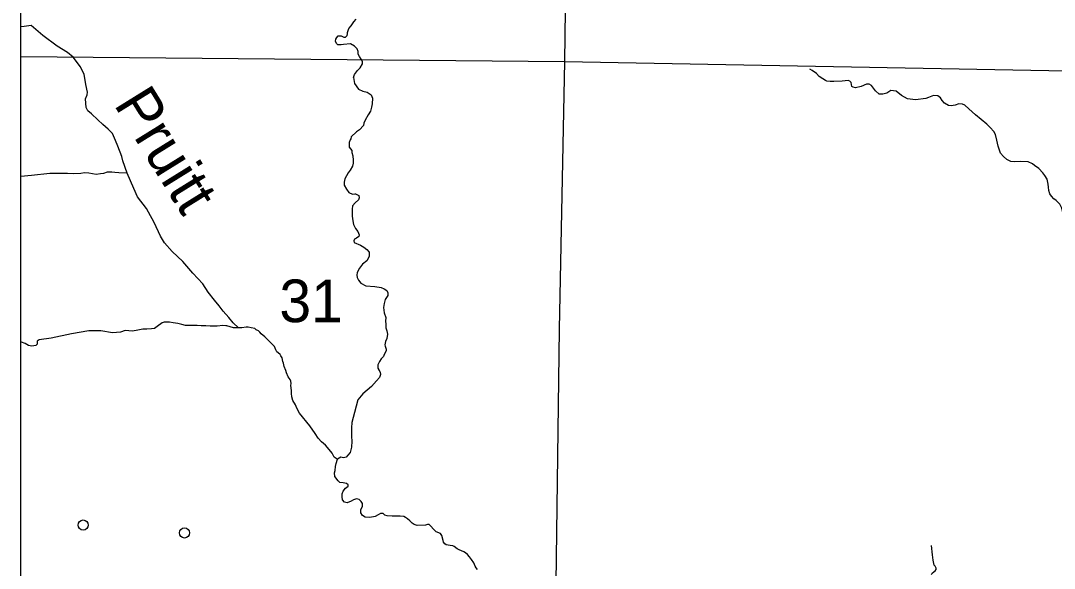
# Model space of a CAD drawing. Extents: x 1369979 to 1371646, y 379997 to 381064.
# Drawn here: x 1370544.5 to 1370664.4, y 380241.9 to 380305.4 of the extents above; entities that cross this region are included whole.
import ezdxf

# ---------------------------------------------------------------- set-up
doc = ezdxf.new("R2010")
doc.units = 0
doc.layers.add('R_Border Notes', color=7, linetype='Continuous')
doc.layers.add('R_No Plot', color=7, linetype='Continuous')

msp = doc.modelspace()

# ---------------------------------------------------------------- linework, layer by layer
at = {"layer": 'R_Border Notes'}
for points in [[(1370607.67, 380306.66), (1370607.61, 380300.72)], [(1370583.12, 380298.87), (1370583.23, 380299.19), (1370583.59, 380299.65), (1370583.91, 380299.98), (1370584.17, 380300.44), (1370584.15, 380300.72), (1370584.02, 380300.98), (1370583.81, 380301.29), (1370583.67, 380301.57), (1370583.67, 380301.87), (1370583.55, 380302.19), (1370583.23, 380302.5), (1370582.77, 380302.74), (1370581.94, 380302.68), (1370581.69, 380302.63), (1370581.3, 380302.65), (1370581.15, 380302.81), (1370581.02, 380303.07), (1370581.07, 380303.31), (1370581.17, 380303.51), (1370581.35, 380303.67), (1370581.68, 380303.69), (1370582, 380303.53), (1370582.18, 380303.54), (1370582.4, 380303.72), (1370582.44, 380303.93), (1370582.44, 380304.09), (1370582.59, 380304.52), (1370582.86, 380304.85), (1370583.15, 380305.3), (1370583.42, 380305.62)], [(1370545.71, 380304.9), (1370544.9, 380304.75), (1370544.5, 380304.74)], [(1370548.72, 380302.48), (1370547.06, 380303.74), (1370545.71, 380304.9)], [(1370552.24, 380297.14), (1370552.06, 380298.04), (1370551.87, 380299.23), (1370551.39, 380300.12), (1370550.96, 380300.72), (1370550.57, 380301.2), (1370549.91, 380301.75), (1370548.72, 380302.48)], [(1370544.5, 380301.3), (1370607.61, 380300.72)], [(1370607.61, 380300.72), (1370606.97, 380269.65), (1370606.6, 380240.19)], [(1370607.61, 380300.72), (1370670.02, 380299.56)], [(1370642.63, 380298.09), (1370642.01, 380297.82), (1370641.38, 380297.66), (1370641.09, 380297.72), (1370640.96, 380297.82), (1370640.9, 380298.04), (1370640.88, 380298.28), (1370640.73, 380298.43), (1370640.51, 380298.49), (1370639.82, 380298.43), (1370638.87, 380298.38), (1370638.44, 380298.38), (1370638.06, 380298.44), (1370637.87, 380298.5), (1370637.57, 380298.68), (1370637.17, 380298.98), (1370636.86, 380299.32), (1370636.36, 380299.66), (1370636.09, 380299.8)], [(1370583.12, 380298.87), (1370583.23, 380298.16), (1370583.68, 380297.51), (1370584.2, 380297.25), (1370584.7, 380297.14), (1370585.16, 380296.85), (1370585.33, 380296.46), (1370585.28, 380295.8), (1370585.21, 380295.41), (1370585.1, 380294.96), (1370584.83, 380294.51), (1370584.46, 380293.89), (1370584.33, 380293.56), (1370584.26, 380293.27), (1370583.81, 380292.8), (1370583.46, 380292.55)], [(1370649.54, 380296.43), (1370648.33, 380296.28), (1370647.4, 380296.36), (1370646.7, 380296.77), (1370646.07, 380297.25), (1370645.48, 380297.35), (1370644.99, 380297.02), (1370644.53, 380296.9), (1370644.12, 380296.93), (1370643.69, 380297.32), (1370643.44, 380297.6), (1370643.24, 380297.91), (1370642.96, 380298.09), (1370642.63, 380298.09)], [(1370556.85, 380287.74), (1370556.35, 380289.19), (1370556.22, 380289.69), (1370555.77, 380290.88), (1370555.51, 380291.54), (1370555.14, 380292.37), (1370554.66, 380292.85), (1370554.03, 380293.4), (1370553.44, 380293.93), (1370552.73, 380294.62), (1370552.3, 380294.98), (1370552.1, 380295.37), (1370552.06, 380295.89), (1370552.03, 380296.38), (1370552.23, 380296.84), (1370552.24, 380297.14)], [(1370656.6, 380293.42), (1370655.29, 380294.51), (1370654.53, 380295.22), (1370654.06, 380295.64), (1370653.77, 380295.77), (1370653.35, 380295.78), (1370652.92, 380295.66), (1370652.49, 380295.58), (1370652.15, 380295.59), (1370651.68, 380295.87), (1370651.42, 380296.18), (1370651.25, 380296.48), (1370650.91, 380296.73), (1370650.44, 380296.76), (1370649.85, 380296.54), (1370649.54, 380296.43)], [(1370661.91, 380288.84), (1370661.42, 380289.06), (1370660.52, 380289.09), (1370659.84, 380289.07), (1370659.38, 380289.1), (1370658.95, 380289.35), (1370658.54, 380289.68), (1370658.21, 380290.09), (1370657.94, 380290.88), (1370657.77, 380291.57), (1370657.62, 380292.23), (1370657.41, 380292.58), (1370657, 380293.07), (1370656.6, 380293.42)], [(1370583.46, 380292.55), (1370582.86, 380291.97), (1370582.8, 380291.75), (1370582.74, 380291.61), (1370582.63, 380291.32), (1370582.63, 380291.05), (1370582.63, 380290.77), (1370582.92, 380290.37), (1370582.92, 380290.17), (1370583.05, 380289.77), (1370583.09, 380289.28), (1370583.07, 380288.93), (1370582.99, 380288.58), (1370582.74, 380288.11), (1370582.48, 380287.78), (1370582.11, 380287.1), (1370582.04, 380286.7), (1370582.04, 380286.37), (1370582.3, 380285.9), (1370582.59, 380285.52), (1370583.02, 380285.33)], [(1370663.72, 380286.49), (1370663.62, 380287.05), (1370663.35, 380287.48), (1370663.1, 380287.79), (1370662.64, 380288.3), (1370662.16, 380288.64), (1370661.91, 380288.84)], [(1370556.85, 380287.74), (1370555.9, 380287.79), (1370555.43, 380287.83), (1370555.08, 380287.87), (1370554.55, 380287.86), (1370554.09, 380287.71), (1370553.74, 380287.66), (1370553.25, 380287.61), (1370552.4, 380287.76), (1370551.9, 380287.79), (1370551.47, 380287.73), (1370550.59, 380287.66), (1370549.94, 380287.71), (1370549.04, 380287.71), (1370547.86, 380287.7), (1370545.75, 380287.5), (1370544.5, 380287.35)], [(1370559.11, 380283.67), (1370558.06, 380285.01), (1370557.64, 380285.98), (1370556.85, 380287.74)], [(1370665.44, 380282.16), (1370665.49, 380282.75), (1370665.42, 380283.19), (1370665.32, 380283.71), (1370665.07, 380284.14), (1370664.78, 380284.45), (1370664.65, 380284.6), (1370664.4, 380284.79), (1370664.12, 380285.07), (1370663.91, 380285.34), (1370663.79, 380285.74), (1370663.78, 380286.14), (1370663.72, 380286.49)], [(1370583.02, 380285.33), (1370583.26, 380285.37), (1370583.33, 380285.37), (1370583.72, 380285.15), (1370583.79, 380284.91), (1370583.71, 380284.67), (1370583.3, 380284.31), (1370582.99, 380283.97), (1370582.95, 380283.58), (1370582.95, 380283.52), (1370582.95, 380282.8), (1370582.99, 380282.44), (1370583.13, 380281.79), (1370583.33, 380281.32), (1370583.62, 380280.99), (1370583.79, 380280.6), (1370583.75, 380280.4), (1370583.48, 380280.22), (1370583.25, 380280.08), (1370583.16, 380279.91), (1370583.19, 380279.73)], [(1370564.46, 380276.14), (1370563.33, 380277.49), (1370562.09, 380278.68), (1370561.2, 380279.66), (1370560.72, 380280.43), (1370560, 380282.03), (1370559.34, 380283.24), (1370559.11, 380283.67)], [(1370583.19, 380279.73), (1370583.92, 380279.42), (1370584.3, 380279.18), (1370584.66, 380278.91), (1370584.92, 380278.59), (1370584.92, 380278.46), (1370584.95, 380278.08), (1370584.67, 380277.59), (1370584.15, 380277.18), (1370583.81, 380276.74), (1370583.56, 380276.23), (1370583.52, 380275.94), (1370583.56, 380275.65), (1370583.69, 380275.36), (1370583.98, 380275), (1370584.53, 380274.7), (1370585.61, 380274.6), (1370586.34, 380274.5), (1370586.67, 380274.35), (1370586.99, 380274.14), (1370587.11, 380273.86), (1370587.09, 380273.55), (1370586.8, 380273.1), (1370586.67, 380272.62), (1370586.59, 380272.18), (1370586.69, 380271.54)], [(1370569.78, 380269.82), (1370569.17, 380270.38), (1370568.64, 380271.01), (1370567.99, 380271.76), (1370567.53, 380272.35), (1370566.98, 380273.02), (1370566.25, 380273.94), (1370565.64, 380274.9), (1370564.46, 380276.14)], [(1370586.69, 380271.54), (1370586.88, 380271), (1370586.82, 380270.57), (1370586.85, 380270.23), (1370586.85, 380269.81), (1370586.98, 380269.45), (1370587.08, 380269.06), (1370586.99, 380268.56), (1370586.83, 380268.22), (1370586.77, 380267.85), (1370586.8, 380267.68), (1370586.89, 380267.33), (1370586.9, 380267.13), (1370586.73, 380266.81), (1370586.64, 380266.62), (1370586.59, 380266.49), (1370586.33, 380266.21), (1370586.13, 380265.92), (1370585.95, 380265.54), (1370585.95, 380265.18), (1370586.07, 380264.91)], [(1370560.91, 380270.4), (1370560.34, 380269.96), (1370560.01, 380269.73), (1370559.69, 380269.68), (1370559.15, 380269.64), (1370558.66, 380269.65), (1370558.08, 380269.54), (1370557.48, 380269.44), (1370556.64, 380269.5), (1370556.08, 380269.31), (1370555.17, 380269.24), (1370553.8, 380269.47), (1370552.42, 380269.48), (1370550.39, 380269.12), (1370548.02, 380268.63), (1370546.64, 380268.42), (1370546.42, 380268.27), (1370546.42, 380268.11), (1370546.42, 380267.91), (1370546.25, 380267.75), (1370545.79, 380267.69), (1370545.4, 380267.77), (1370545.01, 380268.01), (1370544.58, 380268.16)], [(1370569.19, 380269.8), (1370568.41, 380270.03), (1370568.3, 380270.04), (1370567.95, 380270.07), (1370567.28, 380269.99), (1370566.79, 380270), (1370566.5, 380270), (1370565.98, 380270.06), (1370565.45, 380270.06), (1370564.97, 380270.07), (1370564.22, 380270.07), (1370563.61, 380270.09), (1370563.19, 380270.19), (1370562.73, 380270.33), (1370562.19, 380270.39), (1370561.76, 380270.48), (1370561.14, 380270.48), (1370560.91, 380270.4)], [(1370573.96, 380267.63), (1370573.61, 380268), (1370573.35, 380268.27), (1370572.82, 380268.77), (1370572.42, 380269.1), (1370572.24, 380269.31), (1370572.09, 380269.45), (1370571.82, 380269.6), (1370571.66, 380269.74), (1370571.23, 380269.82), (1370570.91, 380269.88), (1370570.68, 380269.88), (1370570.17, 380269.82), (1370569.78, 380269.82), (1370569.19, 380269.8)], [(1370544.58, 380268.16), (1370544.5, 380268.19)], [(1370575.87, 380263.37), (1370575.83, 380263.64), (1370575.76, 380263.83), (1370575.66, 380263.99), (1370575.52, 380264.14), (1370575.35, 380264.59), (1370575.28, 380264.85), (1370575.06, 380265.34), (1370574.98, 380265.73), (1370574.93, 380265.92), (1370574.84, 380266.32), (1370574.69, 380266.55), (1370574.59, 380266.73), (1370574.39, 380266.9), (1370574.22, 380267.03), (1370574.12, 380267.26), (1370574.01, 380267.47), (1370573.96, 380267.63)], [(1370585.95, 380265.18), (1370586.23, 380264.69), (1370586.26, 380264.41), (1370586.13, 380264.05), (1370585.77, 380263.65), (1370585.22, 380262.99), (1370584.2, 380262.17), (1370583.61, 380261.47), (1370583.41, 380260.71), (1370583.23, 380260), (1370582.93, 380258.84), (1370582.87, 380258.23), (1370582.89, 380257.22)], [(1370576.38, 380260.9), (1370576.07, 380261.38), (1370575.98, 380261.82), (1370575.93, 380262.18), (1370575.94, 380262.56), (1370575.86, 380263.14), (1370575.87, 380263.37)], [(1370578.67, 380257.55), (1370578.04, 380258.43), (1370576.87, 380259.91), (1370576.56, 380260.49), (1370576.38, 380260.9)], [(1370582.89, 380257.22), (1370582.94, 380256.67), (1370582.9, 380255.96), (1370582.73, 380255.37), (1370582.47, 380255.04), (1370582.27, 380254.83), (1370581.97, 380254.74), (1370581.66, 380254.8), (1370581.25, 380254.58), (1370581.09, 380254.65), (1370580.89, 380254.81), (1370580.64, 380255.26), (1370580.28, 380255.7), (1370579.85, 380256.22), (1370579.42, 380256.6), (1370579.03, 380257), (1370578.67, 380257.55)], [(1370586.56, 380248.26), (1370586.26, 380248.29), (1370585.99, 380248.14), (1370585.63, 380247.93), (1370585.01, 380247.8), (1370584.46, 380247.85), (1370584.16, 380248.04), (1370583.95, 380248.36), (1370583.97, 380248.7), (1370584.16, 380249.14), (1370584.16, 380249.42), (1370584, 380249.66), (1370583.77, 380249.89), (1370583.46, 380249.97), (1370583.11, 380249.87), (1370582.85, 380249.7), (1370582.39, 380249.51), (1370582.06, 380249.58), (1370581.84, 380249.87), (1370581.81, 380250.22), (1370581.81, 380250.55), (1370581.9, 380250.87), (1370582.2, 380251.2), (1370582.49, 380251.43), (1370582.48, 380251.61), (1370582.29, 380251.74), (1370581.93, 380251.82), (1370581.54, 380251.89), (1370581.33, 380252.08), (1370580.94, 380252.55), (1370580.91, 380252.98), (1370580.98, 380253.26), (1370581.01, 380253.73), (1370581.09, 380254.09), (1370581.25, 380254.58)], [(1370590.51, 380246.87), (1370590.15, 380246.99), (1370589.93, 380247.15), (1370589.64, 380247.43), (1370589.4, 380247.65), (1370589.15, 380247.81), (1370588.95, 380247.91), (1370588.55, 380247.98), (1370587.6, 380247.95), (1370587.02, 380248), (1370586.74, 380248.1), (1370586.56, 380248.26)], [(1370593.54, 380245.14), (1370593.37, 380245.73), (1370593.2, 380245.96), (1370592.71, 380246.15), (1370592.39, 380246.45), (1370592.09, 380246.81), (1370591.89, 380246.99), (1370591.7, 380247), (1370591.47, 380246.92), (1370590.51, 380246.87)], [(1370597.52, 380241.79), (1370597.36, 380241.97), (1370597.23, 380242.16), (1370597.09, 380242.54), (1370596.81, 380242.93), (1370596.56, 380243.24), (1370596.35, 380243.51), (1370596.13, 380243.72), (1370595.93, 380243.84), (1370595.64, 380243.95), (1370595.36, 380244.07), (1370595.15, 380244.16), (1370594.8, 380244.43), (1370594.66, 380244.53), (1370594.35, 380244.58), (1370594.11, 380244.59), (1370593.87, 380244.63), (1370593.71, 380244.75), (1370593.57, 380244.95), (1370593.54, 380245.14)], [(1370650.2, 380241.19), (1370650.27, 380241.37), (1370650.46, 380241.52), (1370650.63, 380241.63), (1370650.75, 380241.79), (1370650.75, 380241.95), (1370650.61, 380242.18), (1370650.51, 380242.3), (1370650.37, 380242.87), (1370650.33, 380243.16), (1370650.32, 380243.49), (1370650.18, 380244.55)]]:
    msp.add_lwpolyline(points, dxfattribs=at)
for centre in [(1370551.74, 380246.94), (1370563.5, 380246.02)]:
    msp.add_circle(centre, 0.586, dxfattribs=at)
at = {"layer": 'R_No Plot'}
msp.add_lwpolyline([(1370544.5, 380586.87), (1371140.38, 380586.87), (1371140.38, 380146.39), (1370544.5, 380146.39)], close=True, dxfattribs=at)

# ---------------------------------------------------------------- texts
at = {"layer": 'R_Border Notes'}
msp.add_text('Pruitt', height=4.95, rotation=301.8031, dxfattribs=at).set_placement((1370555.23, 380295.75))
msp.add_text('31', height=4.95, dxfattribs=at).set_placement((1370574.52, 380270.47))

doc.saveas('drawing.dxf')
